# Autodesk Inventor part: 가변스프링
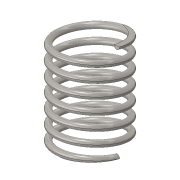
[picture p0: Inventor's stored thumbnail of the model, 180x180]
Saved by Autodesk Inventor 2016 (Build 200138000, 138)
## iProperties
Created: 2020-01
Part Number: 가변스프링
Material: 스테인레스 스틸
Document SubType Name: Modeling
Designer: user
Mass: 10.944 g
Surface Area: 27.6337 cm^2
Volume: 1.368 cm^3
Density: 8 g/cm^3
Appearance: 반연마
Author: user
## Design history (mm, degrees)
sketch "스케치1"
  geometry: L1 (0, 0)-(10, 0); L2 (10, 0)-(10, 28.7); L3 (10, 28.7)-(0, 28.7); L4 (0, 28.7)-(0, 0); C1 r 1 at (10, 0)
  constraints: 8 end point, 2 parallel, 1 centre point, 1 coincident, 1 horizontal, 1 perpendicular
  dimensions: "d0" = 2 diameter of C1; "d1" = 28.7 distance of L1.end L2.end (derived); "d2" = 20 diameter of L2 L4
feature "코일1" sketch "스케치1" pitch "d3" = 10; turns "d5" = 7; dims "d4" = 28.7 (= d1), "d6" = 0, angle "d7" = 90 deg, angle "d8" = 90 deg, "d9" = 0, "d10" = 0
sketch "스케치2"
  geometry: L1 (-9, 0)-(-11, 0) reference; 1 further point
  constraints: 1 horizontal alignment
extrude "돌출1" cut sketch "스케치2" stored distance "d11" = 10; taper "d12" = 0 deg
node "작업 평면1"
sketch "스케치3"
  geometry: L1 (-1, 0)-(1, 0) reference; 1 further point
  constraints: 1 horizontal alignment
extrude "돌출2" cut sketch "스케치3" stored distance "d14" = 10; taper "d15" = 0 deg
node "솔리드1"
node "절단 모서리 투영1"
node "절단 모서리 투영2"
other parameters: "d13" = 90 deg
